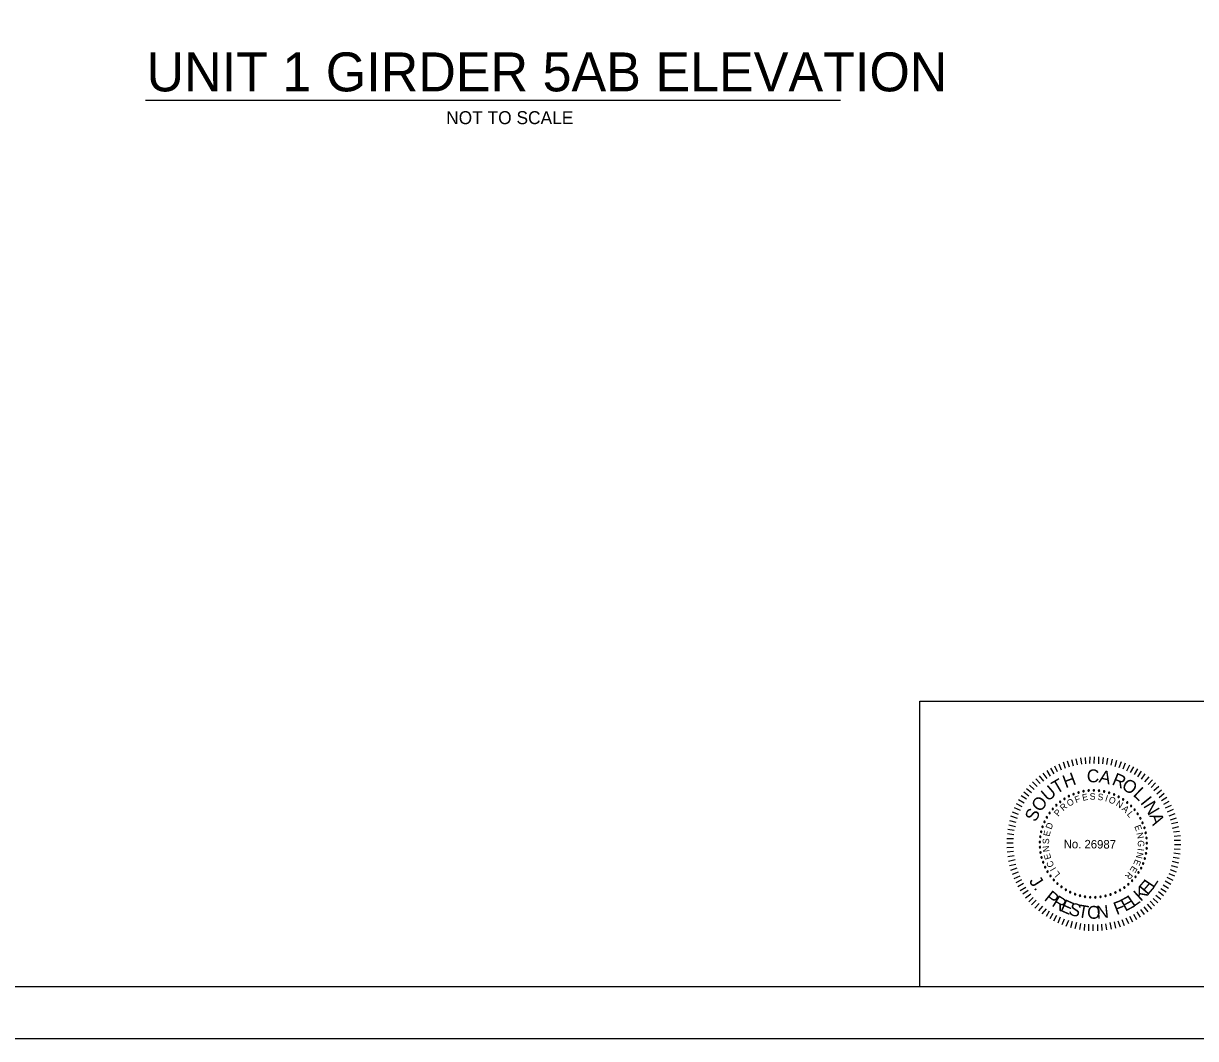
# Model space of a CAD drawing. Extents: x -305 to -161, y -187 to -99.
# Drawn here: x -249.19 to -204.01, y -187.49 to -148.37 of the extents above; entities that cross this region are included whole.
import ezdxf

# ---------------------------------------------------------------- set-up
doc = ezdxf.new("R2010")
doc.units = 0
for name, color, linetype in [('BR_BORDER LINES', 7, 'Continuous'), ('BR_TEXT', 7, 'Continuous'), ('Level 31', 7, 'Continuous')]:
    doc.layers.add(name, color=color, linetype=linetype)

msp = doc.modelspace()

# ---------------------------------------------------------------- linework, layer by layer
at = {"layer": 'BR_BORDER LINES'}
for p, q in [((-214.64, -174.489), (-193.18, -174.489)), ((-214.64, -185.489), (-214.64, -174.489)), ((-297.843, -185.489), (-163.178, -185.489))]:
    msp.add_line(p, q, dxfattribs=at)
at = {"layer": 'BR_TEXT'}
for p, q in [((-244.483, -151.32), (-217.698, -151.32)), ((-208.394, -176.917), (-208.429, -176.673)), ((-208.236, -176.901), (-208.251, -176.657)), ((-208.077, -176.892), (-208.075, -176.634)), ((-207.909, -176.883), (-207.907, -176.636)), ((-207.741, -176.895), (-207.732, -176.637)), ((-207.58, -176.906), (-207.561, -176.663)), ((-207.426, -176.925), (-207.382, -176.681)), ((-209.461, -177.282), (-209.582, -177.065)), ((-209.323, -177.211), (-209.427, -176.987)), ((-209.175, -177.144), (-209.269, -176.92)), ((-209.02, -177.076), (-209.103, -176.842)), ((-208.861, -177.026), (-208.949, -176.795)), ((-208.717, -176.986), (-208.77, -176.742)), ((-208.552, -176.946), (-208.608, -176.709)), ((-207.265, -176.957), (-207.208, -176.721)), ((-207.1, -176.999), (-207.036, -176.756)), ((-206.953, -177.042), (-206.865, -176.813)), ((-206.795, -177.095), (-206.708, -176.862)), ((-206.652, -177.165), (-206.54, -176.942)), ((-206.508, -177.234), (-206.383, -177.012)), ((-206.358, -177.308), (-206.229, -177.093)), ((-209.993, -177.662), (-210.159, -177.482)), ((-209.861, -177.564), (-210.021, -177.363)), ((-209.726, -177.462), (-209.883, -177.258)), ((-209.602, -177.377), (-209.724, -177.16)), ((-206.225, -177.405), (-206.089, -177.19)), ((-206.091, -177.492), (-205.946, -177.291)), ((-205.962, -177.596), (-205.799, -177.398)), ((-205.836, -177.696), (-205.663, -177.519)), ((-210.432, -178.153), (-210.63, -177.993)), ((-210.328, -178.02), (-210.526, -177.864)), ((-210.228, -177.894), (-210.402, -177.724)), ((-210.11, -177.771), (-210.287, -177.594)), ((-205.723, -177.807), (-205.55, -177.634)), ((-205.611, -177.932), (-205.421, -177.765)), ((-205.502, -178.06), (-205.316, -177.907)), ((-205.407, -178.194), (-205.21, -178.038)), ((-210.686, -178.552), (-210.912, -178.441)), ((-210.617, -178.416), (-210.832, -178.287)), ((-210.519, -178.269), (-210.735, -178.137)), ((-205.319, -178.312), (-205.109, -178.183)), ((-205.231, -178.46), (-205.017, -178.335)), ((-205.16, -178.598), (-204.929, -178.49)), ((-210.876, -179.014), (-211.122, -178.923)), ((-210.826, -178.853), (-211.059, -178.766)), ((-210.756, -178.699), (-210.985, -178.598)), ((-205.089, -178.746), (-204.862, -178.648)), ((-205.022, -178.901), (-204.795, -178.817)), ((-210.954, -179.326), (-211.204, -179.262)), ((-210.925, -179.158), (-211.168, -179.098)), ((-204.968, -179.063), (-204.738, -178.976)), ((-204.928, -179.207), (-204.688, -179.151)), ((-204.895, -179.376), (-204.654, -179.316)), ((-211.026, -179.792), (-211.284, -179.79)), ((-211.015, -179.634), (-211.261, -179.605)), ((-210.996, -179.47), (-211.24, -179.437)), ((-204.862, -179.52), (-204.625, -179.491)), ((-204.836, -179.685), (-204.592, -179.66)), ((-204.831, -179.843), (-204.59, -179.845)), ((-211.029, -180.129), (-211.286, -180.133)), ((-211.034, -179.957), (-211.285, -179.955)), ((-211.02, -180.283), (-211.267, -180.312)), ((-204.833, -180.18), (-204.593, -180.189)), ((-204.822, -180.008), (-204.578, -180.01)), ((-211.004, -180.448), (-211.248, -180.484)), ((-210.964, -180.606), (-211.215, -180.659)), ((-204.906, -180.656), (-204.666, -180.713)), ((-204.87, -180.499), (-204.634, -180.538)), ((-204.841, -180.334), (-204.598, -180.367)), ((-210.938, -180.775), (-211.182, -180.831)), ((-210.891, -180.923), (-211.139, -181.006)), ((-210.845, -181.077), (-211.079, -181.161)), ((-205.04, -181.125), (-204.814, -181.213)), ((-204.984, -180.971), (-204.755, -181.059)), ((-204.942, -180.824), (-204.702, -180.885)), ((-210.777, -181.226), (-211.008, -181.334)), ((-210.71, -181.37), (-210.937, -181.489)), ((-210.642, -181.519), (-210.859, -181.644)), ((-205.257, -181.563), (-205.045, -181.692)), ((-205.183, -181.416), (-204.954, -181.538)), ((-205.11, -181.272), (-204.884, -181.384)), ((-210.547, -181.667), (-210.765, -181.792)), ((-210.462, -181.784), (-210.663, -181.93)), ((-210.361, -181.919), (-210.561, -182.075)), ((-210.262, -182.054), (-210.439, -182.217)), ((-205.645, -182.092), (-205.458, -182.258)), ((-205.535, -181.959), (-205.351, -182.118)), ((-205.437, -181.826), (-205.243, -181.975)), ((-205.347, -181.71), (-205.139, -181.839)), ((-210.146, -182.158), (-210.326, -182.338)), ((-210.031, -182.279), (-210.2, -182.463)), ((-209.901, -182.383), (-210.064, -182.57)), ((-209.768, -182.487), (-209.928, -182.678)), ((-206.133, -182.517), (-205.99, -182.71)), ((-206.002, -182.415), (-205.842, -182.605)), ((-205.874, -182.313), (-205.704, -182.5)), ((-205.76, -182.194), (-205.589, -182.377)), ((-209.645, -182.574), (-209.77, -182.782)), ((-209.505, -182.664), (-209.63, -182.879)), ((-209.368, -182.744), (-209.477, -182.967)), ((-209.221, -182.814), (-209.319, -183.037)), ((-209.068, -182.884), (-209.155, -183.11)), ((-208.91, -182.933), (-209.001, -183.166)), ((-208.766, -182.983), (-208.823, -183.219)), ((-208.602, -183.011), (-208.662, -183.258)), ((-207.15, -182.996), (-207.09, -183.233)), ((-207.002, -182.949), (-206.918, -183.183)), ((-206.843, -182.902), (-206.759, -183.13)), ((-206.699, -182.835), (-206.591, -183.059)), ((-206.554, -182.768), (-206.432, -182.992)), ((-206.402, -182.69), (-206.277, -182.907)), ((-206.268, -182.602), (-206.135, -182.812)), ((-208.444, -183.057), (-208.484, -183.29)), ((-208.287, -183.076), (-208.306, -183.323)), ((-208.129, -183.087), (-208.131, -183.335)), ((-207.961, -183.099), (-207.963, -183.343)), ((-207.792, -183.09), (-207.787, -183.338)), ((-207.631, -183.081), (-207.616, -183.329)), ((-207.476, -183.065), (-207.437, -183.299)), ((-207.315, -183.022), (-207.262, -183.27))]:
    msp.add_line(p, q, dxfattribs=at)
for centre, start, end in [((-208.706, -178.067), 21.6807, 201.6807), ((-208.517, -178.003), 16.1422, 196.1422), ((-208.517, -178.003), 196.1422, 16.1422), ((-208.323, -177.957), 10.6038, 190.6038), ((-208.323, -177.957), 190.6038, 10.6038), ((-208.126, -177.93), 5.0653, 185.0653), ((-208.126, -177.93), 185.0653, 5.0653), ((-207.926, -177.923), 359.5268, 179.5268), ((-207.926, -177.923), 179.5268, 359.5268), ((-207.727, -177.934), 173.9884, 353.9884), ((-207.727, -177.934), 353.9884, 173.9884), ((-207.531, -177.965), 168.4499, 348.4499), ((-207.531, -177.965), 348.4499, 168.4499), ((-207.338, -178.015), 162.9114, 342.9114), ((-207.338, -178.015), 342.9114, 162.9114), ((-209.373, -178.495), 43.8345, 223.8345), ((-209.373, -178.495), 223.8345, 43.8345), ((-209.223, -178.364), 38.2961, 218.2961), ((-209.223, -178.364), 218.2961, 38.2961), ((-209.06, -178.248), 32.7576, 212.7576), ((-209.06, -178.248), 212.7576, 32.7576), ((-208.887, -178.149), 27.2191, 207.2191), ((-208.887, -178.149), 207.2191, 27.2191), ((-208.706, -178.067), 201.6807, 21.6807), ((-207.15, -178.083), 157.373, 337.373), ((-207.15, -178.083), 337.373, 157.373), ((-206.97, -178.169), 151.8345, 331.8345), ((-206.97, -178.169), 331.8345, 151.8345), ((-206.8, -178.272), 146.2961, 326.2961), ((-206.8, -178.272), 326.2961, 146.2961), ((-206.639, -178.39), 140.7576, 320.7576), ((-206.639, -178.39), 320.7576, 140.7576), ((-209.74, -178.964), 60.4499, 240.4499), ((-209.74, -178.964), 240.4499, 60.4499), ((-209.633, -178.796), 54.9114, 234.9114), ((-209.633, -178.796), 234.9114, 54.9114), ((-209.511, -178.639), 49.373, 229.373), ((-209.511, -178.639), 229.373, 49.373), ((-206.492, -178.524), 135.2191, 315.2191), ((-206.492, -178.524), 315.2191, 135.2191), ((-206.357, -178.671), 129.6807, 309.6807), ((-206.357, -178.671), 309.6807, 129.6807), ((-206.238, -178.831), 124.1422, 304.1422), ((-206.238, -178.831), 304.1422, 124.1422), ((-209.903, -179.328), 71.5268, 251.5268), ((-209.903, -179.328), 251.5268, 71.5268), ((-209.83, -179.142), 65.9884, 245.9884), ((-209.83, -179.142), 245.9884, 65.9884), ((-206.135, -179.001), 118.6038, 298.6038), ((-206.135, -179.001), 298.6038, 118.6038), ((-206.048, -179.181), 113.0653, 293.0653), ((-206.048, -179.181), 293.0653, 113.0653), ((-205.979, -179.368), 107.5268, 287.5268), ((-205.979, -179.368), 287.5268, 107.5268), ((-209.993, -179.716), 82.6038, 262.6038), ((-209.993, -179.716), 262.6038, 82.6038), ((-209.957, -179.52), 77.0653, 257.0653), ((-209.957, -179.52), 257.0653, 77.0653), ((-205.929, -179.561), 101.9884, 281.9884), ((-205.929, -179.561), 281.9884, 101.9884), ((-205.897, -179.758), 96.4499, 276.4499), ((-205.897, -179.758), 276.4499, 96.4499), ((-210.009, -179.914), 88.1422, 268.1422), ((-210.006, -180.114), 93.6807, 273.6807), ((-209.984, -180.312), 99.2191, 279.2191), ((-210.009, -179.914), 268.1422, 88.1422), ((-210.006, -180.114), 273.6807, 93.6807), ((-209.984, -180.312), 279.2191, 99.2191), ((-205.892, -180.156), 85.373, 265.373), ((-205.885, -179.957), 90.9114, 270.9114), ((-205.892, -180.156), 265.373, 85.373), ((-205.885, -179.957), 270.9114, 90.9114), ((-209.943, -180.507), 104.7576, 284.7576), ((-209.943, -180.507), 284.7576, 104.7576), ((-209.884, -180.697), 110.2961, 290.2961), ((-209.884, -180.697), 290.2961, 110.2961), ((-206.026, -180.737), 68.7576, 248.7576), ((-206.026, -180.737), 248.7576, 68.7576), ((-205.963, -180.548), 74.2961, 254.2961), ((-205.963, -180.548), 254.2961, 74.2961), ((-205.918, -180.353), 79.8345, 259.8345), ((-205.918, -180.353), 259.8345, 79.8345), ((-209.806, -180.881), 115.8345, 295.8345), ((-209.806, -180.881), 295.8345, 115.8345), ((-209.711, -181.056), 121.373, 301.373), ((-209.711, -181.056), 301.373, 121.373), ((-209.599, -181.221), 126.9114, 306.9114), ((-209.599, -181.221), 306.9114, 126.9114), ((-206.207, -181.092), 57.6807, 237.6807), ((-206.207, -181.092), 237.6807, 57.6807), ((-206.108, -180.918), 63.2191, 243.2191), ((-206.108, -180.918), 243.2191, 63.2191), ((-209.472, -181.375), 132.4499, 312.4499), ((-209.472, -181.375), 312.4499, 132.4499), ((-209.331, -181.515), 137.9884, 317.9884), ((-209.331, -181.515), 317.9884, 137.9884), ((-209.177, -181.642), 143.5268, 323.5268), ((-209.177, -181.642), 323.5268, 143.5268), ((-206.752, -181.667), 35.5268, 215.5268), ((-206.752, -181.667), 215.5268, 35.5268), ((-206.596, -181.543), 41.0653, 221.0653), ((-206.596, -181.543), 221.0653, 41.0653), ((-206.452, -181.406), 46.6038, 226.6038), ((-206.452, -181.406), 226.6038, 46.6038), ((-206.321, -181.255), 52.1422, 232.1422), ((-206.321, -181.255), 232.1422, 52.1422), ((-209.011, -181.753), 149.0653, 329.0653), ((-209.011, -181.753), 329.0653, 149.0653), ((-208.836, -181.847), 154.6038, 334.6038), ((-208.836, -181.847), 334.6038, 154.6038), ((-208.652, -181.924), 160.1422, 340.1422), ((-208.652, -181.924), 340.1422, 160.1422), ((-208.462, -181.983), 165.6807, 345.6807), ((-208.462, -181.983), 345.6807, 165.6807), ((-208.267, -182.023), 171.2191, 351.2191), ((-208.267, -182.023), 351.2191, 171.2191), ((-208.068, -182.045), 356.7576, 176.7576), ((-208.068, -182.045), 176.7576, 356.7576), ((-207.869, -182.047), 2.2961, 182.2961), ((-207.869, -182.047), 182.2961, 2.2961), ((-207.67, -182.029), 7.8345, 187.8345), ((-207.67, -182.029), 187.8345, 7.8345), ((-207.474, -181.993), 13.373, 193.373), ((-207.474, -181.993), 193.373, 13.373), ((-207.283, -181.938), 18.9114, 198.9114), ((-207.283, -181.938), 198.9114, 18.9114), ((-207.098, -181.865), 24.4499, 204.4499), ((-207.098, -181.865), 204.4499, 24.4499), ((-206.92, -181.774), 29.9884, 209.9884), ((-206.92, -181.774), 209.9884, 29.9884)]:
    msp.add_arc(centre, 0.028, start, end, dxfattribs=at)
at = {"layer": 'Level 31'}
msp.add_lwpolyline([(-305.176, -187.489), (-161.176, -187.489), (-161.176, -99.489), (-305.176, -99.489)], close=True, dxfattribs=at)

# ---------------------------------------------------------------- texts
at = {"layer": 'BR_TEXT'}
for s, height, p in [('UNIT 1 GIRDER 5AB ELEVATION', 1.5, (-244.448, -150.983)), ('NOT TO SCALE', 0.5, (-232.898, -152.247))]:
    msp.add_text(s, height=height, dxfattribs=at).set_placement(p)
for s, height, rotation, p in [('C', 0.496, 359.5482, (-208.2, -177.612)), ('T', 0.496, 30.4992, (-209.37, -178.076)), ('H', 0.496, 20.3637, (-209.018, -177.846)), ('A', 0.496, 348.1981, (-207.755, -177.609)), ('R', 0.496, 337.4344, (-207.262, -177.689)), ('O', 0.496, 326.5869, (-206.893, -177.836)), ('U', 0.496, 40.8022, (-209.694, -178.375)), ('S', 0.249, 2.208, (-208.081, -178.286)), ('L', 0.496, 315.9488, (-206.442, -178.107)), ('O', 0.496, 52.0267, (-209.993, -178.79)), ('R', 0.249, 40.3949, (-209.107, -178.737)), ('O', 0.249, 30.8477, (-208.882, -178.561)), ('F', 0.249, 20.6127, (-208.613, -178.417)), ('E', 0.249, 11.4103, (-208.352, -178.33)), ('S', 0.249, 352.6608, (-207.796, -178.287)), ('I', 0.249, 343.1136, (-207.515, -178.335)), ('O', 0.249, 338.4392, (-207.381, -178.376)), ('N', 0.249, 328.2042, (-207.103, -178.501)), ('I', 0.496, 308.6613, (-206.157, -178.404)), ('N', 0.496, 300.7037, (-206.035, -178.521)), ('S', 0.496, 63.2511, (-210.174, -179.173)), ('P', 0.249, 49.9421, (-209.299, -178.947)), ('A', 0.249, 318.657, (-206.867, -178.662)), ('L', 0.249, 309.4546, (-206.668, -178.851)), ('A', 0.496, 289.4792, (-205.798, -178.894)), ('D', 0.249, 69.0364, (-209.567, -179.448)), ('E', 0.249, 291.049, (-206.372, -179.312)), ('S', 0.249, 87.786, (-209.656, -179.999)), ('E', 0.249, 78.2388, (-209.633, -179.715)), ('No. 26987', 0.327, 359.5268, (-209.092, -180.153)), ('N', 0.249, 281.8466, (-206.283, -179.572)), ('N', 0.249, 97.3332, (-209.632, -180.283)), ('I', 0.249, 262.4084, (-206.238, -180.149)), ('G', 0.249, 272.2995, (-206.237, -179.853)), ('E', 0.249, 106.5355, (-209.564, -180.549)), ('C', 0.249, 116.4266, (-209.444, -180.819)), ('E', 0.249, 248.1867, (-206.328, -180.563)), ('N', 0.249, 257.7339, (-206.256, -180.287)), ('I', 0.249, 121.1011, (-209.372, -180.939)), ('L', 0.249, 129.9595, (-209.209, -181.147)), ('R', 0.249, 229.782, (-206.591, -181.044)), ('E', 0.249, 238.9844, (-206.44, -180.814)), ('J', 0.494, 302.9559, (-210.441, -181.421)), ('K', 0.494, 42.3031, (-206.118, -182.229)), ('E', 0.494, 49.3639, (-205.857, -181.989)), ('L', 0.494, 56.4247, (-205.627, -181.718)), ('.', 0.494, 309.3974, (-210.264, -181.693)), ('P', 0.494, 321.1035, (-209.871, -182.13)), ('R', 0.494, 328.5359, (-209.578, -182.362)), ('E', 0.494, 28.1814, (-206.719, -182.605)), ('L', 0.494, 35.2422, (-206.407, -182.436)), ('E', 0.494, 335.9684, (-209.257, -182.555)), ('S', 0.494, 343.0292, (-208.932, -182.698)), ('T', 0.494, 350.4617, (-208.573, -182.804)), ('O', 0.494, 358.1419, (-208.192, -182.863)), ('N', 0.494, 5.8221, (-207.805, -182.872)), ('F', 0.494, 21.1206, (-207.05, -182.735))]:
    msp.add_text(s, height=height, rotation=rotation, dxfattribs=at).set_placement(p)

doc.saveas('drawing.dxf')
